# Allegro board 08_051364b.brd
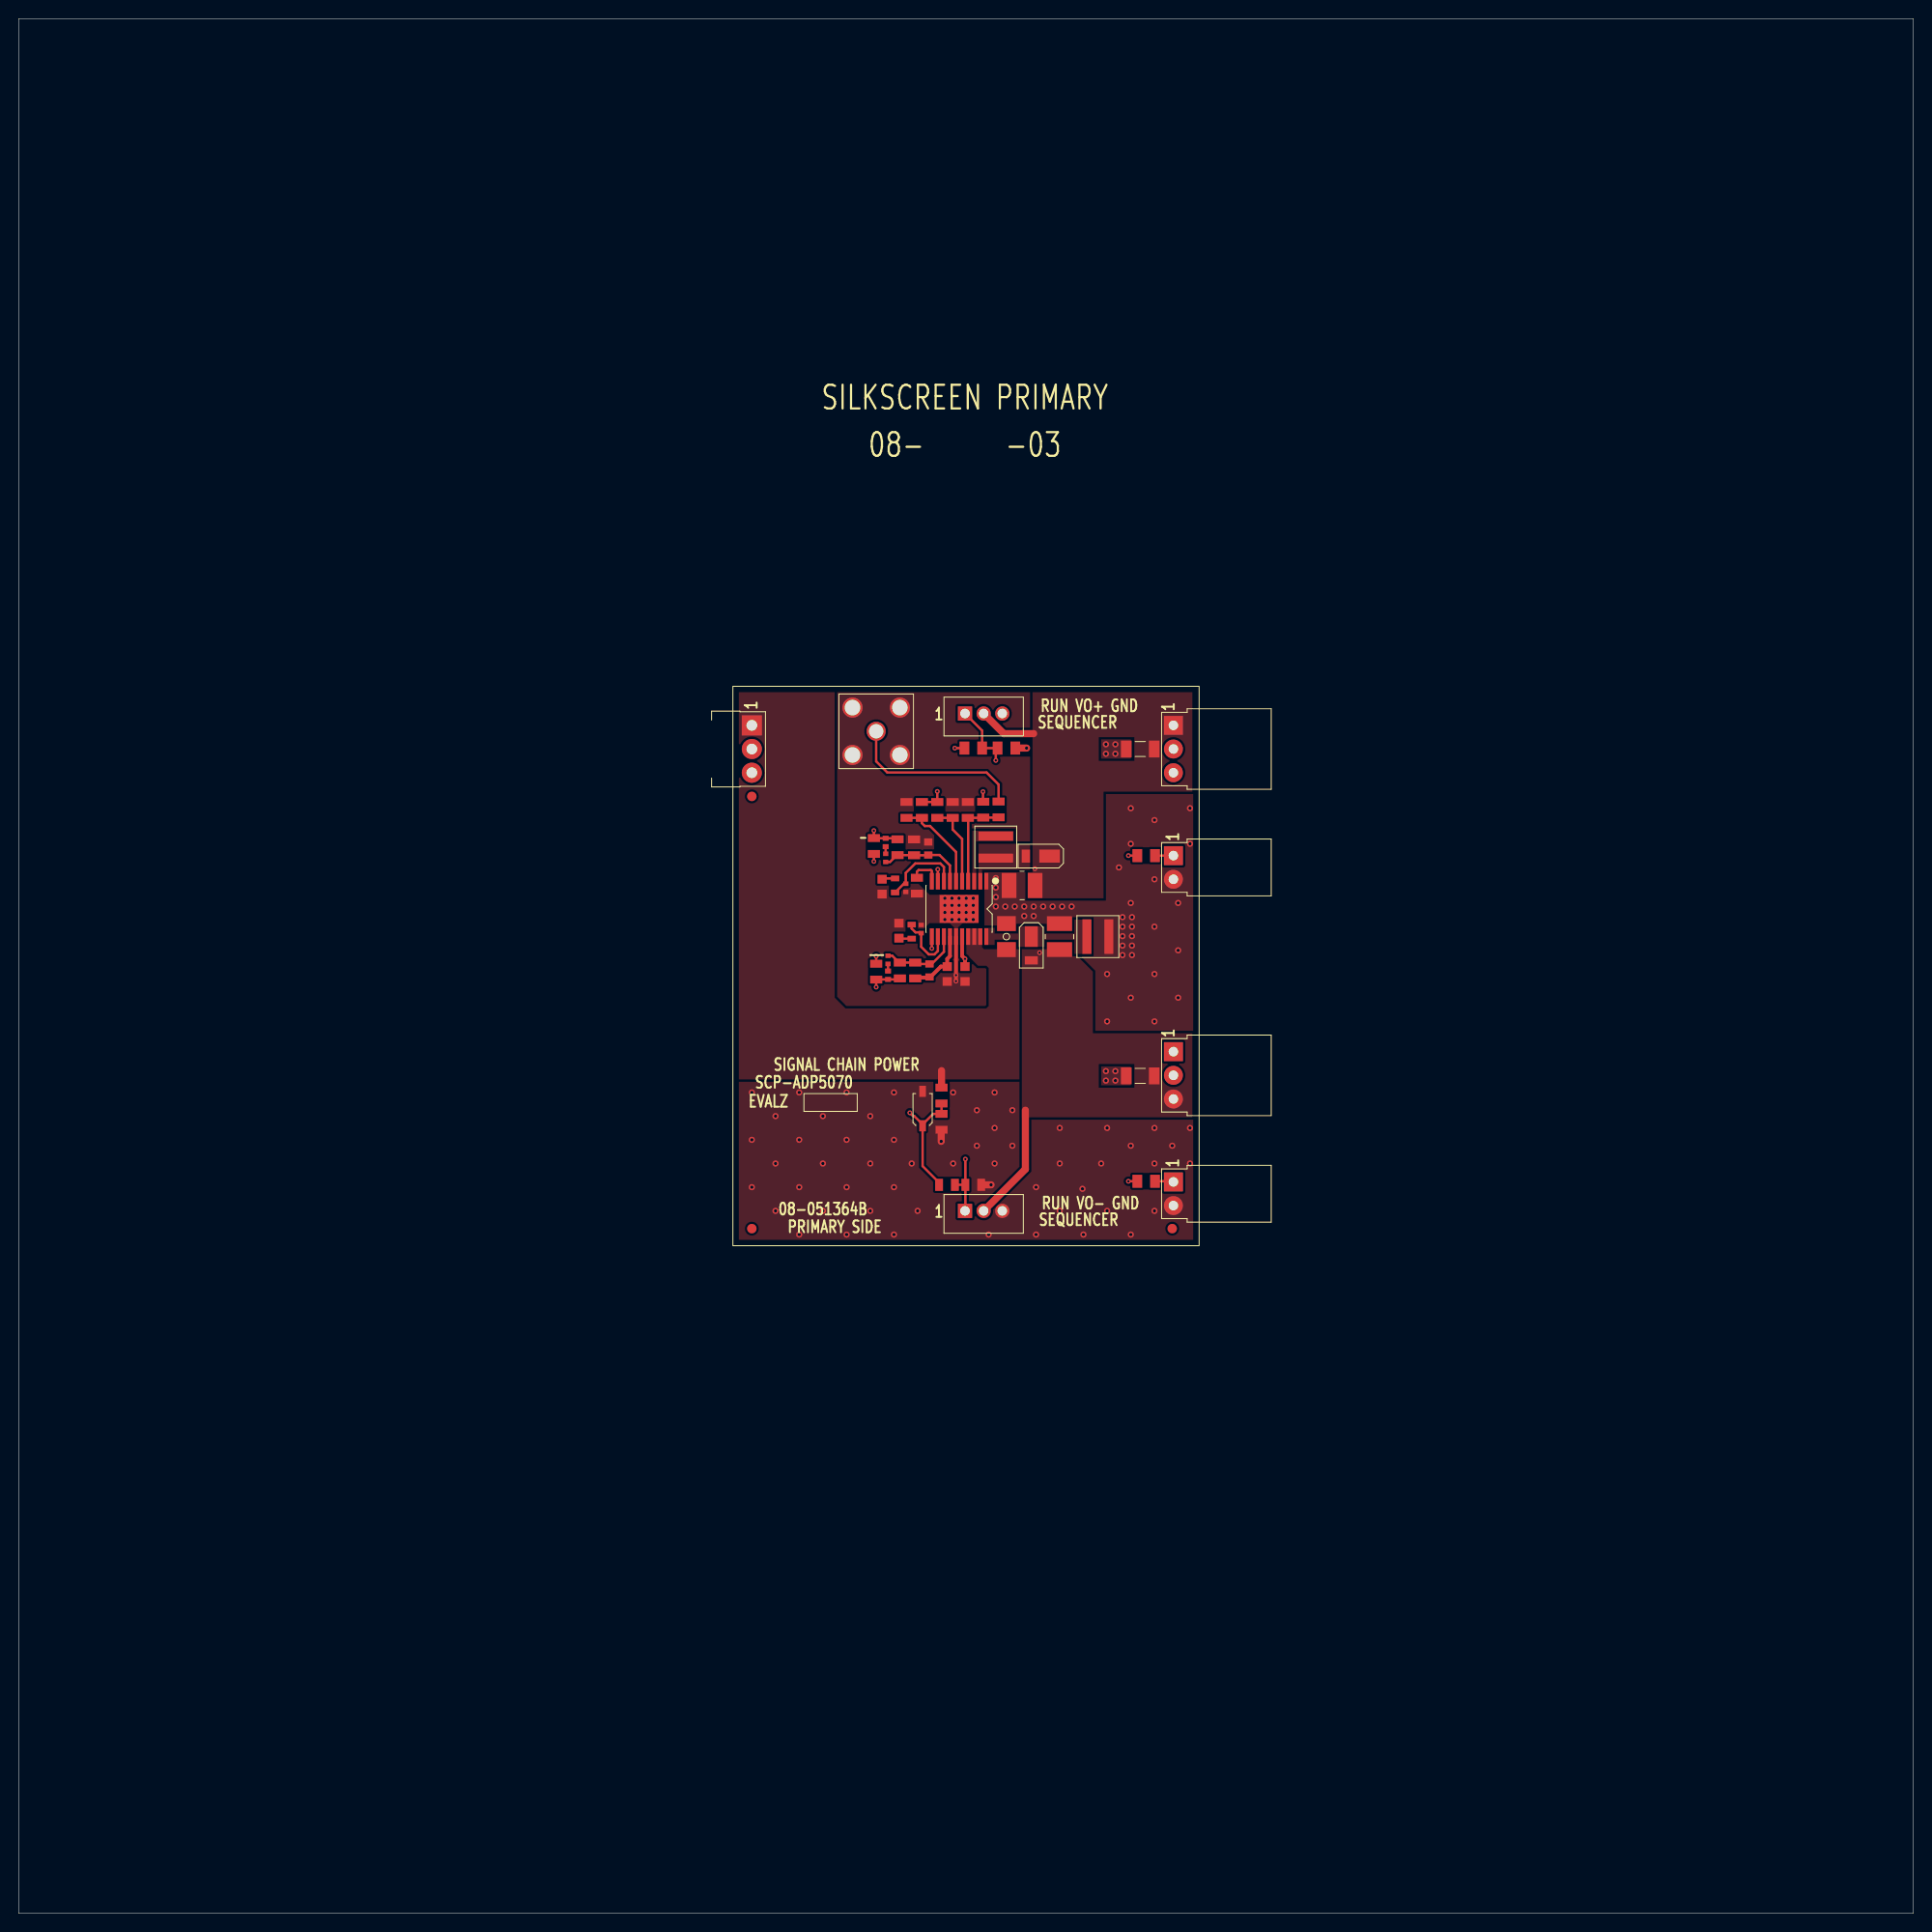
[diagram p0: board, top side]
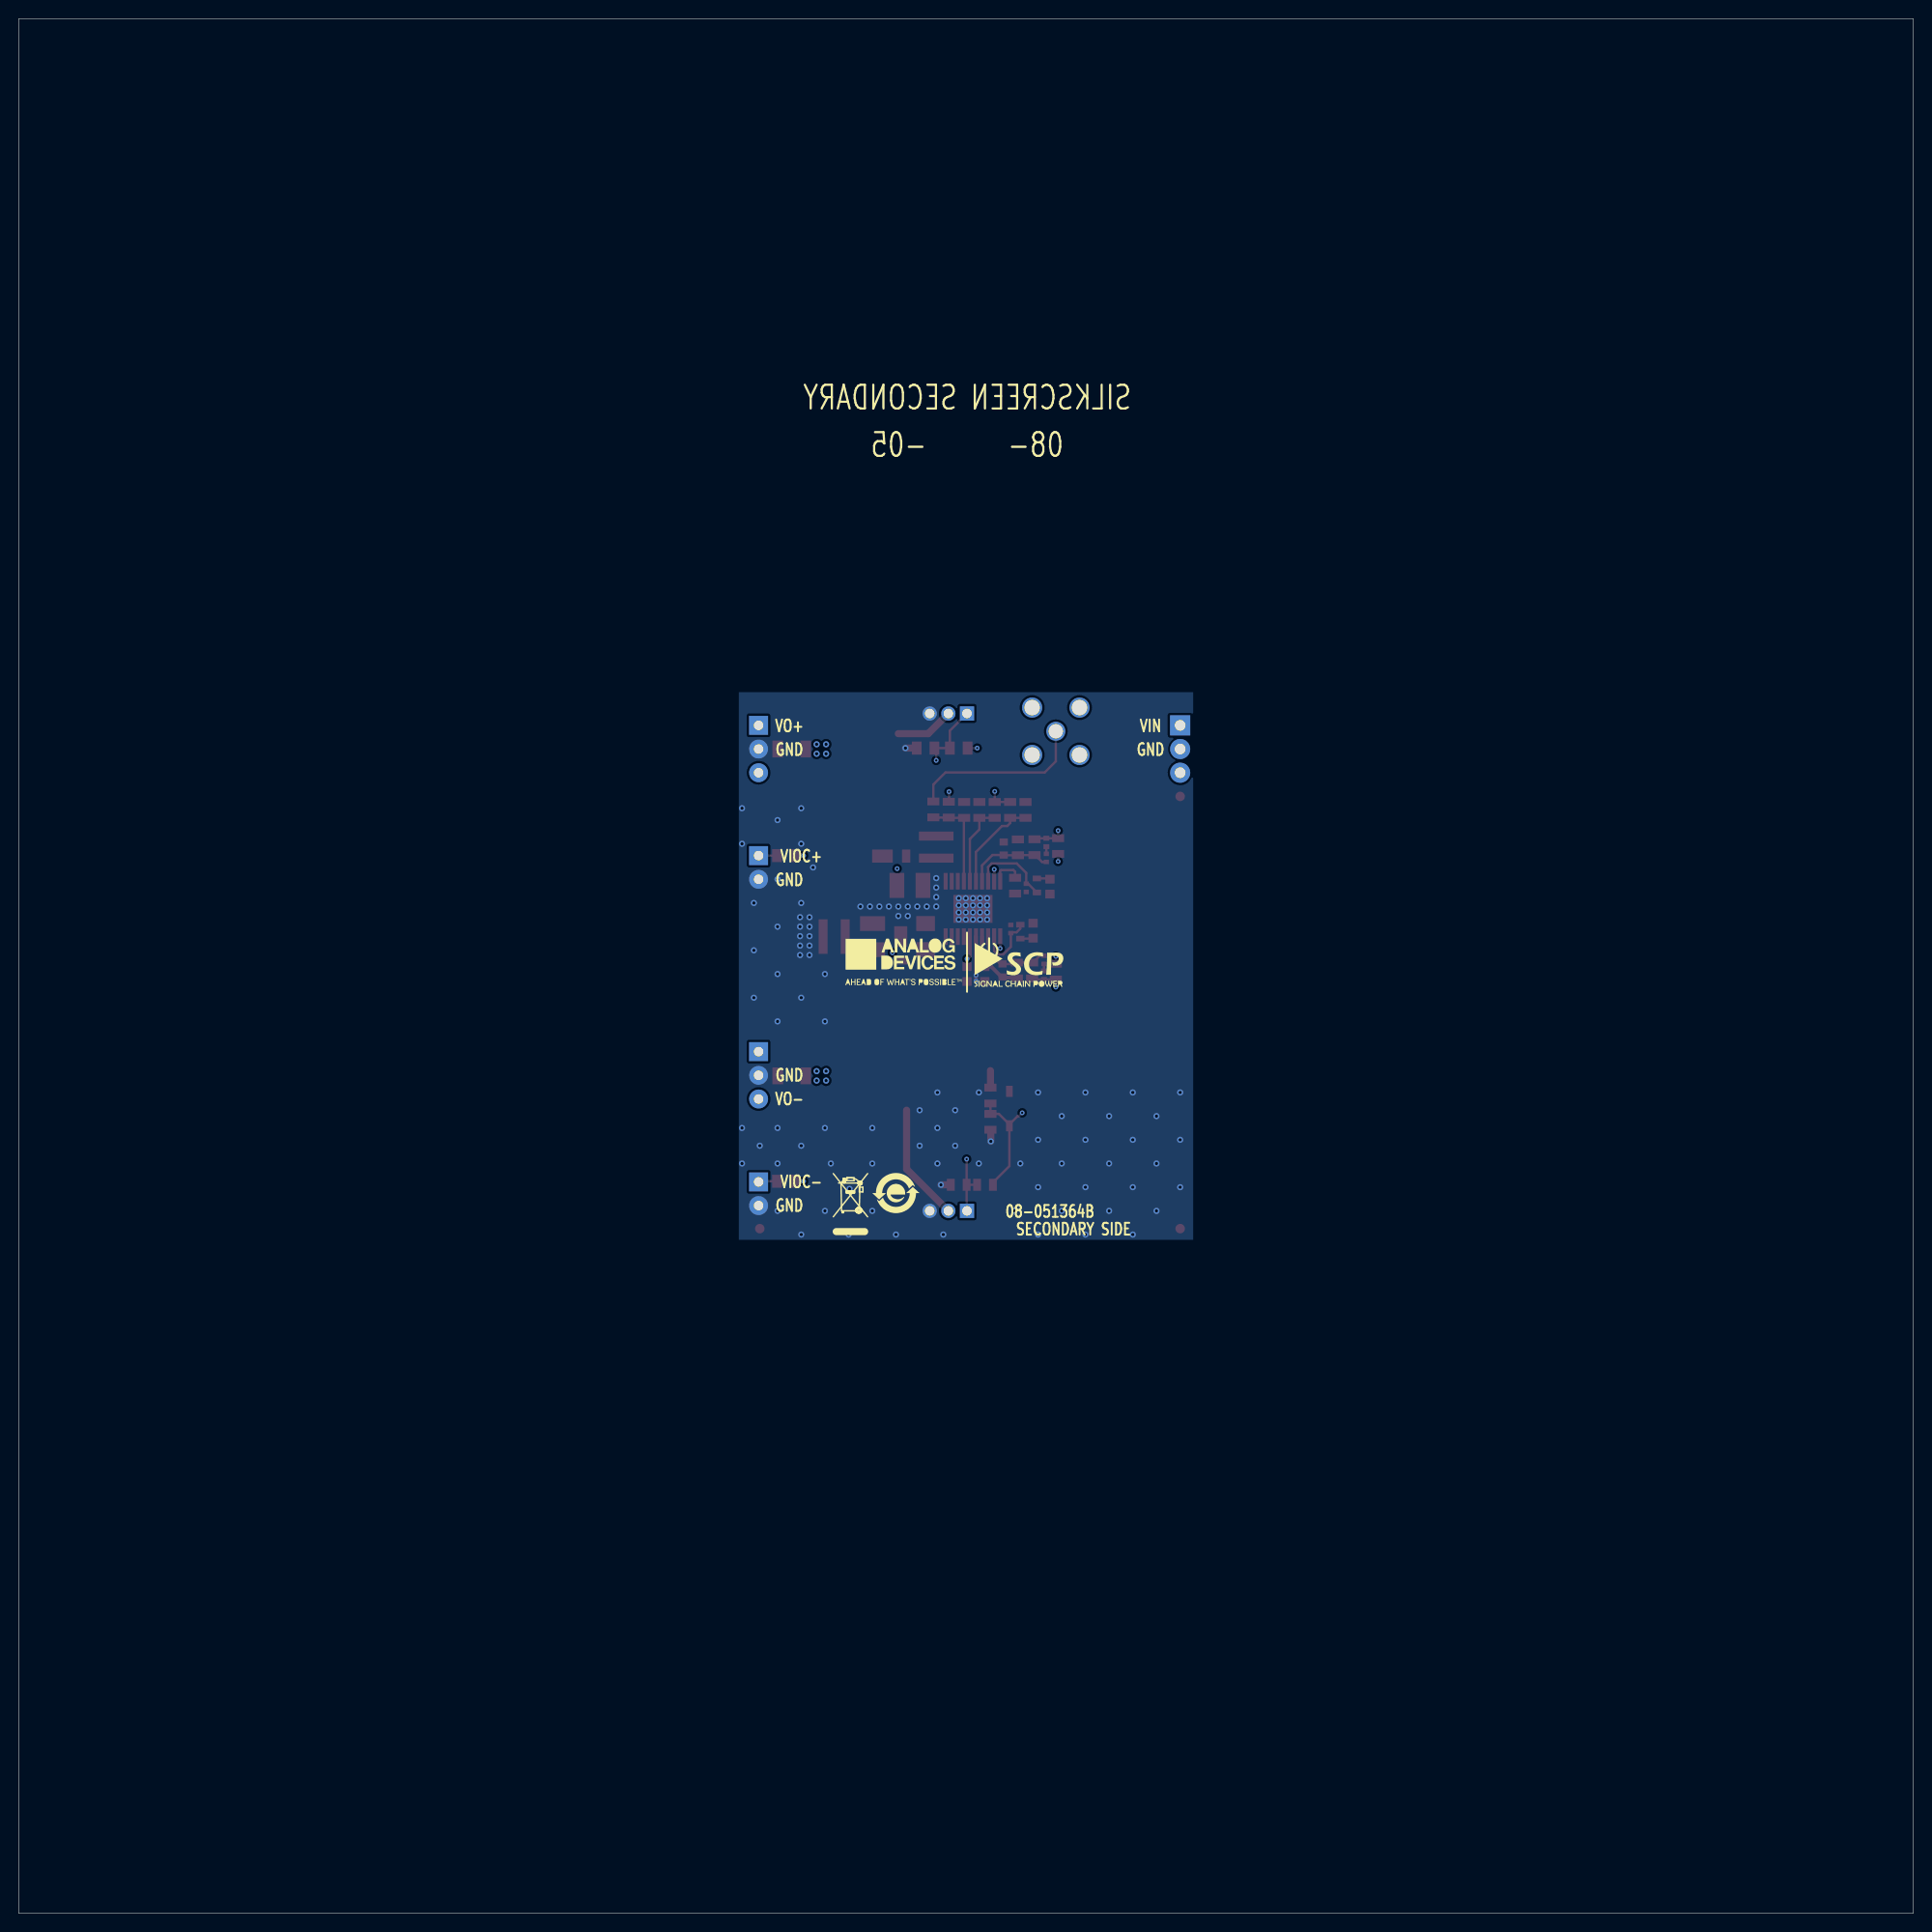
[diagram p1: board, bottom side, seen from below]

Outline 203.2 x 203.2 mm; copper layers: TOP, L2_GND, L3_SIG, BOTTOM. Coordinates in mm from the lower left corner of the outline.
Outline path: 0,203.2 203.2,203.2 203.2,0 0,0 0,203.2

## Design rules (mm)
constraint set DEFAULT: min track width 0.203

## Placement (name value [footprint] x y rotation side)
CC1  0.047uF  [C0603]  92.6 110.11 90 top
CC2  0.068uF  [C0603]  94.41 105.39 270 top
CFF1  TBD0402  [C0402]  92.98 113.2 270 top
CFF2  TBD0402  [C0402]  93.24 102.26 270 top
CHF3  TBD0402  [C0402]  95.14 109.98 270 top
CHF4  TBD0402  [C0402]  96.79 105.56 90 top
CIN1  10UF  [C1206H71]  105.94 104.75 90 top
COPT1  TBD0603  [C0603#2]  97.56 114.2 90 top
COPT2  TBD0603  [C0603#2]  97.68 101.12 90 top
COUT1  10uF  [C1210-2]  107.61 110.24 180 top
COUT1B  TBD1206  [C1206]  120.29 124.87 180 top
COUT2  10uF  [C1210-2]  111.63 104.75 270 top
COUT2B  TBD1206  [C1206]  120.29 89.82 0 top
CVREF  1UF  [C0603]  99.59 100.74 270 top
CVREG  1UF  [C0603]  101.49 100.74 270 top
D1  DFLS240-7  [DSML110W70H39]  109.62 113.39 180 top
D2  DFLS240-7  [DSML110W70H39]  108.6 103.81 270 top
D3  MMSZ5233B-7-F  [SOD123-3]  96.95 86.31 90 top
INPUT  PBC03SBAN  [CNTHMHDRRA1X3L300W100H145]  78.63 127.41 270 top
L1  6.8uH  [LSMSQ157H122]  104.79 114.35 90 top
L2  15uH  [LSMSQ157H161]  115.74 104.75 0 top
NOREF  -  []  78.63 127.41 0 top
NOREF#2  -  []  126.6 71.6 90 top
NOREF#3  -  []  126.6 71.6 90 top
NOREF#4  -  []  76.6 131.6 0 top
NOREF#5  -  []  126.6 131.6 180 top
NOREF#6  -  []  -273.05 -196.85 0 top
NOREF#7  -  []  76.6 131.6 0 top
NOREF#8  -  []  154.53 243.13 0 top
NOREF#9  -  []  -273.05 -196.85 0 top
NOREF#10  -  []  175.2 132.31 0 top
NOREF#11  -  []  30.04 19.38 0 top
NOREF#12  -  []  76.6 131.6 0 top
NOREF#13  -  []  185.95 28.91 0 top
NOREF#14  -  []  20.54 -100.96 0 top
NOREF#15  -  [unnamed#2]  78.63 119.79 0 top
NOREF#16  -  [unnamed#2]  123.72 73.43 0 top
NOREF#17  -  []  101.47 156.34 0 top
NOREF#18  -  []  78.63 127.41 0 top
NOREF#19  -  []  76.6 131.6 270 top
NOREF#20  -  [unnamed#2]  78.63 73.43 0 top
NOREF#21  -  []  76.6 71.6 0 top
NOREF#22  -  []  108.6 102.01 180 bottom
NOREF#23  -  []  109.11 77.24 180 bottom
NOREF#24  -  []  114.19 72.8 180 bottom
NOREF#25  -  []  95.9 102.01 180 bottom
OUTPUT1  PPPC031LGBN-RC  [CNHDRRA1X3H108]  123.84 127.41 270 top
OUTPUT2  PPPC031LGBN-RC  [CNHDRRA1X3H108]  123.84 92.42 270 top
P1  53253-0370  [CNTHMHDR1X3L315W144H224]  101.49 128.68 0 top
P2  53253-0370  [CNTHMHDR1X3L315W144H224]  101.49 75.34 0 top
R1  14.3K  [R0805]  98.98 87.71 270 top
R2  11K  [R0805]  98.98 84.89 270 top
R3  0  [R0805#2]  102.38 124.97 0 top
R4  TBD0805  [R0805#2]  105.94 124.97 0 top
R5  0  [R0805]  99.56 78.13 0 top
R6  TBD0805  [R0805]  102.38 78.13 0 top
R7  TBD0805  [R0805]  98.52 118.34 270 top
R8  TBD0805  [R0805]  100.17 118.34 90 top
R9  0  [R0805]  103.45 118.37 270 top
R10  TBD0805  [R0805]  101.8 118.34 90 top
R11  TBD0805  [R0805]  105.1 118.39 270 top
R12  TBD0805  [R0805]  96.34 110.21 270 top
R13  TBD0805  [R0805]  96.87 118.34 270 top
R14  TBD0805  [R0805]  95.22 118.34 90 top
R15  0  [R0805]  91.72 114.47 90 top
R16  0  [R0805]  91.97 100.99 270 top
R17  TBD0805  [R0805#2]  120.92 113.44 180 top
R18  TBD0805  [R0805#2]  120.92 78.51 0 top
RC1  12K  [R0603]  94 110.24 270 top
RC2  10K  [R0603]  95.78 105.29 90 top
RFB1  137K  [R0805]  96.03 114.33 270 top
RFB2  118K  [R0805]  96.16 101.12 270 top
RFF1  TBD0402  [R0402]  92.98 114.85 90 top
RFF2  TBD0402  [R0402]  93.24 100.61 270 top
RFT1  2.43MEG  [R0805]  94.25 114.34 270 top
RFT2  2.32MEG  [R0805]  94.51 101.12 270 top
SYNC  5-1814832-1  [CNTYCO1814832]  91.97 126.77 0 top
U1  ADP5070AREZ  [TSSOP20_PAD4_2X3]  100.86 107.72 180 top
VIOC1  PPPC021LGBN-RC  [CNTHFHDRRA1X2L220W335H108]  123.84 113.44 270 top
VIOC2  PPPC021LGBN-RC  [CNTHFHDRRA1X2L220W335H108]  123.84 78.45 270 top

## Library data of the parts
CC1 = CAP: User Part Number: UPN; Tolerance: 10; alternate symbols: (); part number: CAP_SM-0.047UF,16V,10,E022362,C0603; tolerance: 10
CC2 = CAP: User Part Number: UPN; Tolerance: 10; alternate symbols: (); part number: CAP_SM-0.068UF,16V,10,E022339,C0603; tolerance: 10
CFF1 CFF2 CHF3 CHF4 = CAP: User Part Number: UPN; alternate symbols: (C0402L_ALT); part number: CAP_SM-TBD0402,TBD0402,TBD0402,E000381,C0402; room: ADP5070_BOTTOM
CIN1 = CAP: Tolerance: 10; User Part Number: UPN; alternate symbols: (); part number: CAP_SM-10UF,25V,10,E022363,C1206H71; tolerance: 10
COPT1 COPT2 = CAP: User Part Number: UPN; alternate symbols: (C0603L, C0603L_ALT); part number: CAP_SM-TBD0603,TBD0603,TBD0603,E000382,C0603
COUT1 COUT2 = CAP: Tolerance: 10; User Part Number: UPN; alternate symbols: (); part number: CAP_SM-10UF,50V,10,E022361,C1210-2; tolerance: 10
COUT1B COUT2B = CAP: User Part Number: UPN; alternate symbols: (); part number: CAP_SM-TBD1206,TBD1206,TBD1206,E000384,C1206
CVREF CVREG = CAP: User Part Number: UPN; Tolerance: 10; alternate symbols: (); part number: CAP_SM-1UF,10V,10,E033698,C0603; tolerance: 10
D1 D2 = DIOSCHOTTKY: Tolerance: N/A; User Part Number: UPN; alternate symbols: (); part number: DIOSCHOTTKY_SM-DFLS240-7,40V,N/A,E019969,DSML110W70H39; tolerance: N/A
D3 = DIOZNR: Tolerance: 5; User Part Number: UPN; alternate symbols: (); part number: DIOZNR_SM-MMSZ5233B-7-F,N/A,5,E017917,SOD123-3; tolerance: 5
INPUT = CN3P: Tolerance: N/A; User Part Number: UPN; alternate symbols: (CNTHMHDRRA1X3L300W100H145_SCP); part number: CN3P_TH-PBC03SBAN,E034137,CNTHMHDRRA1X3L300W100H145; tolerance: N/A
L1 = IND: User Part Number: UPN; Tolerance: 20; alternate symbols: (); part number: IND_SM-6.8UH,20,E017909,LSMSQ157H122; tolerance: 20
L2 = IND: User Part Number: UPN; Tolerance: 20; alternate symbols: (); part number: IND_SM-15UH,20,E022386,LSMSQ157H161; tolerance: 20
OUTPUT1 OUTPUT2 = CN3P: User Part Number: UPN; Tolerance: N/A; alternate symbols: (CNHDRRA1X3H108_SCP); part number: CN3P_TH-PPPC031LGBN-RC,E034111,CNHDRRA1X3H108; tolerance: N/A
P1 P2 = CN3P: Tolerance: N/A; User Part Number: UPN; alternate symbols: (); part number: CN3P_TH-53253-0370,E033940,CNTHMHDR1X3L315W144H224; tolerance: N/A
R1 = RES: User Part Number: UPN; Tolerance: 1; alternate symbols: (R0805L); part number: RES_SM-14.3K,E012818,1/8W,1,R0805; tolerance: 1
R2 = RES: User Part Number: UPN; Tolerance: 1; alternate symbols: (R0805L); part number: RES_SM-11K,E003538,1/8W,1,R0805; tolerance: 1
R3 R5 R9 R15 R16 = RES: User Part Number: UPN; Tolerance: N/A; alternate symbols: (R0805L); part number: RES_SM-0,E004152,1/10W,N/A,R0805; tolerance: N/A
R4 R6-R8 R10-R14 R17 R18 = RES: User Part Number: UPN; alternate symbols: (R0805L); part number: RES_SM-TBD0805,E004051,TBD0805,TBD0805,R0805
RC1 = RES: User Part Number: UPN; Tolerance: 1; alternate symbols: (R0603L); part number: RES_SM-12K,E018193,1/10W,1,R0603; tolerance: 1
RC2 = RES: User Part Number: UPN; Tolerance: 1; alternate symbols: (R0603L); part number: RES_SM-10K,E017856,1/16W,1,R0603; tolerance: 1
RFB1 = RES: User Part Number: UPN; Tolerance: 1; alternate symbols: (R0805L); part number: RES_SM-137K,E003652,1/8W,1,R0805; tolerance: 1
RFB2 = RES: User Part Number: UPN; Tolerance: 1; alternate symbols: (R0805L); part number: RES_SM-118K,E020283,1/8W,1,R0805; tolerance: 1
RFF1 RFF2 = RES: User Part Number: UPN; alternate symbols: (R0402L,R0402L_ALT); part number: RES_SM-TBD0402,E004049,TBD0402,TBD0402,R0402; room: ADP5070_BOTTOM
RFT1 = RES: User Part Number: UPN; Tolerance: 1; alternate symbols: (R0805L); part number: RES_SM-2.43MEG,E022341,1/8W,1,R0805; tolerance: 1
RFT2 = RES: User Part Number: UPN; Tolerance: 1; alternate symbols: (R0805L); part number: RES_SM-2.32MEG,E022342,1/8W,1,R0805; tolerance: 1
SYNC = CNBNC5P: Tolerance: N/A; User Part Number: UPN; alternate symbols: (); part number: CNBNC5P_TH-5-1814832-1,E010606,CNTYCO1814832; tolerance: N/A
U1 = ADP5070_V2: Tolerance: N/A; User Part Number: UPN; alternate symbols: (); part number: ADP5070_V2_SM-ADP5070AREZ,E017326,TSSOP20_PAD4_2X3; tolerance: N/A
VIOC1 VIOC2 = CN2P: Tolerance: N/A; User Part Number: UPN; alternate symbols: (CNTHFHDRRA1X2L220W335H108_SCP); part number: CN2P_TH-PPPC021LGBN-RC,E034113,CNTHFHDRRA1X2L220W335H108; tolerance: N/A

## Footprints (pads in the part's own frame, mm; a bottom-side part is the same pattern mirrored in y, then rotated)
C0402
  rect 0.483x0.559 smd: 1(-0.438,0) 2(0.438,0)
C0603
  rect 0.94x0.991 smd: 1(-0.8,0) 2(0.8,0)
C0603#2
  rect 0.762x0.889 smd: 1(-0.7,0) 2(0.7,0)
C1206
  rect 1.143x1.803 smd: 1(-1.5,0) 2(1.5,0)
C1206H71
  rect 1.6x2.007 smd: 1(-1.397,0) 2(1.397,0)
C1210-2
  rect 1.575x2.692 smd: 1(-1.397,0) 2(1.397,0)
CNHDRRA1X3H108
  rect 2.032x2.032 hole 1.016: 1(0,0)
  round 2.032 hole 1.016: 2(2.54,0) 3(5.08,0)
CNTHFHDRRA1X2L220W335H108
  rect 2.032x2.032 hole 1.016: 1(0,0)
  round 2.032 hole 1.016: 2(2.54,0)
CNTHMHDR1X3L315W144H224
  rect 1.524x1.524 hole 1.016: 1(0,0)
  round 1.524 hole 1.016: 2(2,0) 3(4,0)
CNTHMHDRRA1X3L300W100H145
  rect 2.159x2.159 hole 1.143: 1(0,0)
  round 2.159 hole 1.143: 2(2.54,0) 3(5.08,0)
CNTYCO1814832
  round 2.032 hole 1.524: 1(0,0)
  round 2.159 hole 1.651: 2(-2.54,2.54) 3(2.54,2.54) 4(2.54,-2.54) 5(-2.54,-2.54)
DSML110W70H39
  rect 0.889x1.397 smd: A(1.605,0)
  rect 2.21x1.397 smd: C(-0.945,0)
LSMSQ157H122
  rect 0.965x3.708 smd: 1(-1.181,0) 2(1.181,0)
LSMSQ157H161
  rect 0.965x3.708 smd: 1(-1.181,0) 2(1.181,0)
R0402
  rect 0.533x0.635 smd: 1(-0.45,0) 2(0.45,0)
R0603
  rect 0.61x0.889 smd: 1(-0.75,0) 2(0.75,0)
R0805
  rect 0.838x1.295 smd: 1(-0.85,0) 2(0.85,0)
R0805#2
  rect 1.041x1.397 smd: 1(-0.95,0) 2(0.95,0)
SOD123-3
  rect 1.194x0.711 smd: A(1.847,0) C(-1.847,0)
TSSOP20_PAD4_2X3
  rect 0.432x1.778 smd: 1(-2.925,-2.97) 2(-2.275,-2.97) 3(-1.625,-2.97) 4(-0.975,-2.97) 5(-0.325,-2.97) 6(0.325,-2.97) 7(0.975,-2.97) 8(1.625,-2.97) 9(2.275,-2.97) 10(2.925,-2.97) 11(2.925,2.97) 12(2.275,2.97) 13(1.625,2.97) 14(0.975,2.97) 15(0.325,2.97) 16(-0.325,2.97) 17(-0.975,2.97) 18(-1.625,2.97) 19(-2.275,2.97) 20(-2.925,2.97)
  rect 4.191x2.997 smd: PAD(0,0)
unnamed#2
  round 1.016 smd: (0,0)

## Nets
AGND: CC1.1 CC2.1 CHF3.2(N2) CHF4.2(N2) CIN1.2(N2) COPT1.2(N2) COUT1.2(N2) COUT1B.2(N2) COUT2.1 COUT2B.1 CVREF.2(N2) CVREG.2(N2) D3.A(P) INPUT.2 L2.2(N2) OUTPUT1.2 OUTPUT2.2 P1.3(N3) P2.3(N3) R2.2(N2) R4.2(N2) R6.2(N2) R8.2(N2) R10.2(N2) R12.2(N2) R14.2(N2) RFB1.1 SYNC.2 SYNC.3 SYNC.4 SYNC.5(SH4) U1.1 U1.15 U1.PAD VIOC1.2(N2) VIOC2.2(N2)
VIN+: CIN1.1 INPUT.1 R1.1 U1.17 U1.18 U1.19
COMP1: CHF3.1 RC1.2(N2) U1.8
COMP2: CHF4.1 RC2.2(N2) U1.12
EN1: P1.1 R3.2(N2) R4.1 U1.9
EN2: P2.1 R5.2(N2) R6.1 U1.11
FB1: CFF1.2(N2) COPT1.1 RFB1.2(N2) RFT1.2(N2) U1.7
FB2: CFF2.1 COPT2.2(N2) RFB2.1 RFT2.1 U1.13
INBK: L1.2(N2) U1.3
SEQ: R7.2(N2) R8.1 U1.5
SLEW: R13.2(N2) R14.1 U1.6
SS: R12.1 U1.10
SW1: D1.A(P) L1.1 U1.2
SW2: D2.C L2.1 U1.20
SYNC: R9.2(N2) R10.1 R11.2(N2) U1.4
UNNAMED_2_CAP_I20_N2: CC1.2(N2) RC1.1
UNNAMED_2_CAP_I23_N1: CFF1.1 RFF1.1
UNNAMED_2_CAP_I30_N2: CC2.2(N2) RC2.1
UNNAMED_2_CAP_I33_N2: CFF2.2(N2) RFF2.1
UNNAMED_2_CN2P_I108_N1: R17.1 VIOC1.1
UNNAMED_2_CN2P_I109_N1: R18.2(N2) VIOC2.1
UNNAMED_2_CNBNC5P_I90_CNTR: R11.1 SYNC.1
UNNAMED_2_RES_I134_N2: R15.2(N2) R17.2(N2) RFF1.2(N2) RFT1.1
UNNAMED_2_RES_I135_N1: R16.2(N2) R18.1 RFF2.2(N2) RFT2.2(N2)
V_EN: D3.C R1.2(N2) R2.1 R3.1 R5.1
VO+: COUT1.1 COUT1B.1 D1.C OUTPUT1.1 P1.2 R15.1
VO-: COUT2.2(N2) COUT2B.2(N2) D2.A(P) OUTPUT2.3(N3) P2.2 R16.1
VREF: COPT2.1 CVREF.1 RFB2.2(N2) U1.14
VREG: CVREG.1 R7.1 R9.1 R13.1 U1.16(VREG)

Pads without a net: INPUT 3; OUTPUT1 3; OUTPUT2 1

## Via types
v1: diameter 0.508, hole 0.254, TOP to BOTTOM, 19 vias
v2: diameter 0.66, hole 0.356, TOP to BOTTOM, 126 vias

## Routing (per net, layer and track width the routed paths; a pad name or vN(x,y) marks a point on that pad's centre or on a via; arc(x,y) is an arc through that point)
AGND: length 8.3
  TOP w0.406: 100.53,99.97 v1(100.53,99.98) v1(100.53,100.61) 100.53,100.62 U1.15
  TOP w0.762: R6.2 v2(104.29,78.13) ; R4.2 v2(108.1,124.97) ; 98.94,84.03 v2(98.94,82.79)
  vias: v2(78.63,88.04) v2(78.63,82.96) v2(78.63,77.88) v2(81.17,85.5) v2(81.17,80.42) v2(81.17,75.34) v2(83.71,88.04) v2(83.71,82.96) v2(83.71,77.88) v2(83.71,72.8) v2(86.25,85.5) v2(86.25,80.42) v2(86.25,75.34) v2(88.79,88.04) v2(88.79,82.96) v2(88.79,77.88) v2(88.79,72.8) v2(91.33,85.5) v2(91.33,80.42) v2(91.33,75.34) v2(93.87,88.04) v2(93.87,82.96) v2(93.87,77.88) v2(93.87,72.8) v2(95.78,80.42) v2(96.41,75.34) v2(99.33,108.87) v2(99.33,108.1) v2(99.33,107.34) v2(99.33,106.58) v2(100.1,108.87) v2(100.1,108.1) v2(100.1,107.34) v2(100.1,106.58) v2(100.22,88.04) v2(100.22,80.42) v2(100.86,108.87) v2(100.86,108.1) v2(100.86,107.34) v2(100.86,106.58) v2(101.62,108.87) v2(101.62,108.1) v2(101.62,107.34) v2(101.62,106.58) v2(102.38,108.87) v2(102.38,108.1) v2(102.38,107.34) v2(102.38,106.58) v2(102.76,86.13) v2(102.76,82.32) v2(104.03,72.8) v2(104.67,88.04) v2(104.67,84.23) v2(104.67,80.42) v2(104.79,111.03) v2(104.79,110.01) v2(104.79,108.99) v2(104.79,107.98) v2(105.81,107.98) v2(106.57,86.13) v2(106.57,82.32) v2(106.83,107.98) v2(107.84,107.98) v2(107.84,106.96) v2(108.86,107.98) v2(108.86,106.96) v2(109.11,77.88) v2(109.11,72.8) v2(109.87,107.98) v2(110.89,107.98) v2(111.65,84.23) v2(111.65,80.42) v2(111.65,75.34) v2(111.91,107.98) v2(112.92,107.98) v2(114.09,77.7) v2(114.19,72.8) v2(116.1,80.42) v2(116.61,125.38) v2(116.61,124.36) v2(116.61,90.32) v2(116.61,89.31) v2(116.73,100.74) v2(116.73,95.66) v2(116.73,84.23) v2(116.73,75.34) v2(117.62,125.38) v2(117.62,124.36) v2(117.62,90.32) v2(117.62,89.31) v2(118,112.17) v2(118.38,106.83) v2(118.38,105.82) v2(118.38,104.8) v2(118.38,103.79) v2(118.38,102.77) v2(119.27,118.52) v2(119.27,114.71) v2(119.27,108.36) v2(119.27,98.2) v2(119.27,82.32) v2(119.27,72.8) v2(119.4,106.83) v2(119.4,105.82) v2(119.4,104.8) v2(119.4,103.79) v2(119.4,102.77) v2(121.81,117.25) v2(121.81,110.9) v2(121.81,105.82) v2(121.81,100.74) v2(121.81,95.66) v2(121.81,84.23) v2(121.81,80.42) v2(121.81,75.34) v2(123.72,82.32) v2(124.35,108.36) v2(124.35,103.28) v2(124.35,98.2) v2(125.62,118.52) v2(125.62,114.71) v2(125.62,84.23) v2(125.62,80.42)
VIN+: length 1.8
  TOP w0.762: R1.1 98.98,90.38
COMP1: length 8.9
  TOP w0.254: RC1.2 94.93,110.42 CHF3.1 95.14,111.58 96.16,112.6 98.85,112.6 99.23,112.22 U1.8
COMP2: length 6.9
  TOP w0.254: U1.12 98.58,103.21 98.22,102.85 97.61,102.85 96.79,103.66 CHF4.1 96.71,105.21 96.18,105.21 95.78,105.62 RC2.2
EN1: length 40.1
  TOP w0.254: U1.9 98.58,111.95 v1(98.57,111.97) ; v1(104.79,123.65) 104.79,124.78 R4.1 R3.2 103.33,126.84 P1.1
  L3_SIG w0.254: v1(98.57,111.97) 91.13,111.97 90.65,112.45 90.65,116.54 93.19,119.08 103.7,119.08 104.79,120.17 v1(104.79,123.65)
EN2: length 42.3
  TOP w0.254: R6.1 101.53,75.38 P2.1 ; R6.1 R5.2 ; R6.1 v1(101.53,80.89) ; U1.11 97.93,103.49 v1(97.94,103.48)
  L3_SIG w0.254: v1(101.53,80.89) 101.53,88 90.7,98.83 90.7,103.02 91.46,103.79 97.63,103.79 v1(97.94,103.48)
FB1: length 9.4
  TOP w0.254: CFF1.2 93.45,112.76 94.18,113.49 RFT1.2 96.02,113.49 RFB1.2 97.53,113.48 COPT1.1 98.76,113.5 99.88,112.38 U1.7
FB2: length 8.5
  TOP w0.254: CFF2.1 93.69,102.7 94.42,101.97 RFT2.1 RFB2.1 96.31,101.82 COPT2.2 97.92,101.82 99.23,103.13 U1.13
SEQ: length 8.9
  TOP w0.254: R7.2 R8.1 100.17,116.23 101.18,115.22 U1.5
SLEW: length 10.3
  TOP w0.254: R14.1 R13.2 96.87,116.92 97.17,116.61 97.75,116.61 100.53,113.83 U1.6
SS: length 3.5
  TOP w0.254: U1.10 97.93,111.79 97.83,111.89 96.51,111.89 96.34,111.71 R12.1
SYNC: length 10.1
  TOP w0.254: U1.4 101.83,117.46 R10.1 103.42,117.49 R9.2 105.07,117.52 R11.2
UNNAMED_2_CAP_I20_N2: length 1.4
  TOP w0.254: RC1.1 92.68,110.99 CC1.2
UNNAMED_2_CAP_I23_N1: length 0.8
  TOP w0.254: CFF1.1 RFF1.1
UNNAMED_2_CAP_I30_N2: length 1.4
  TOP w0.254: CC2.2 94.46,104.54 RC2.1
UNNAMED_2_CAP_I33_N2: length 0.8
  TOP w0.254: RFF2.1 CFF2.2
UNNAMED_2_CN2P_I108_N1: length 2
  TOP w0.254: R17.1 VIOC1.1
UNNAMED_2_CN2P_I109_N1: length 2
  TOP w0.254: R18.2 123.78,78.51 VIOC2.1
UNNAMED_2_CNBNC5P_I90_CNTR: length 19.2
  TOP w0.254: SYNC.1 91.97,123.55 93.16,122.35 103.8,122.35 105.1,121.06 R11.1
UNNAMED_2_RES_I134_N2: length 32.8
  TOP w0.254: R17.2 v1(119.02,113.44) ; RFT1.1 94.15,115.3 RFF1.2 91.74,115.3 R15.2 v1(91.72,116.12)
  L3_SIG w0.254: v1(91.72,116.12) 93.77,114.07 118.38,114.07 v1(119.02,113.44)
UNNAMED_2_RES_I135_N1: length 40
  TOP w0.254: RFT2.2 94.4,100.16 RFF2.2 91.99,100.16 R16.2 v1(91.97,99.34) ; R18.1 v1(119.02,78.51)
  L3_SIG w0.254: v1(119.02,78.51) 98.19,99.34 v1(91.97,99.34)
V_EN: length 63.3
  TOP w0.254: v1(95.57,85.85) 95.93,85.5 96.06,85.5 96.95,84.61 ; v1(100.4,124.97) R3.1 ; 96.95,84.61 98.07,85.74 R2.1 R1.2 ; 96.95,84.61 D3.C 96.95,80.14 98.71,78.37 R5.1
  L3_SIG w0.254: v1(95.57,85.85) 95.57,92.31 88.54,99.34 88.54,117.63 92.48,121.57 97,121.57 v1(100.4,124.97)
VO+: length 24.7
  TOP w0.254: R15.1 v1(91.72,112.82)
  TOP w0.762: P1.2 105.65,126.52 108.86,126.52
  L3_SIG w0.305: v1(91.72,112.82) 91.83,112.93 108.1,112.93 v1(108.99,112.04)
VO-: length 32.3
  TOP w0.254: R16.1 v1(91.97,102.64)
  TOP w0.762: P2.2 107.97,79.82 107.97,86.13
  L3_SIG w0.305: v1(91.97,102.64) 93.34,101.27 107.74,101.27 v1(109.49,103.02)
VREF: length 7.3
  TOP w0.406: RFB2.2 96.25,100.36 97.62,100.36 COPT2.1 97.78,100.42 98.9,101.54 CVREF.1 99.59,102.36 99.88,102.66 U1.14
VREG: length 44
  TOP w0.254: v1(103.42,120.3) 103.42,119.24 R9.1 ; R13.1 R7.1 v1(98.52,120.32)
  TOP w0.406: U1.16 101.18,102.67 v1(101.49,102.36) CVREG.1
  L3_SIG w0.254: v1(101.49,102.36) 93.92,109.93 90.62,109.93 89.58,110.98 89.58,117.07 92.83,120.32 v1(98.52,120.32) 103.4,120.32 v1(103.42,120.3)

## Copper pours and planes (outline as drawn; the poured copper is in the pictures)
AGND on TOP: 99.1,99.47 99.1,100.41 101.97,100.41 101.97,99.47
AGND on TOP: 119.27,125.88 119.27,123.85 116.1,123.85 116.1,125.88
AGND on TOP: 77.24,130.96 125.96,130.96 125.96,125.88 119.27,125.88 119.27,123.85 116.48,123.85 116.48,122.58 125.96,122.58 125.96,92.1 119.02,92.1 119.02,90.83 119.27,90.83 119.27,88.8 125.96,88.8 125.96,72.24 77.24,72.24 ; 15 cut-outs
AGND on BOTTOM: 77.24,130.96 125.96,130.96 125.96,72.24 77.24,72.24 ; 9 cut-outs
AGND on L2_GND: 107.33,89.18 107.33,85.12 125.95,85.12 125.95,72.24 77.24,72.24 77.24,89.18
AGND on L2_GND: 107.97,108.87 107.97,108.61 116.61,108.61 116.61,120.04 125.96,120.04 125.96,94.64 115.46,94.64 115.46,101.12 113.81,102.77 113.81,106.58 113.56,106.58 113.56,102.64 115.21,100.99 115.21,94.39 125.88,94.39 125.88,85.37 107.59,85.37 107.59,103.41 109.75,103.41 109.75,106.58 109.49,106.58 109.49,103.66 107.59,103.66 107.59,106.58 107.33,106.58 107.33,89.44 77.24,89.44 77.24,123.47 77.24,123.47 77.24,130.96 87.52,130.96 87.52,98.2 88.67,97.06 103.78,97.06 104.03,97.31 104.03,103.15 104.41,103.53 104.41,106.58 104.16,106.58 104.16,103.66 103.78,103.28 103.78,97.44 103.65,97.31 88.79,97.31 87.78,98.33 87.78,130.96 108.48,130.96 108.48,111.66 108.73,111.66 108.73,130.96 125.88,130.96 125.88,120.3 116.35,120.3 116.35,108.87 ; 4 cut-outs
AGND on L3_SIG: 77.24,130.96 125.96,130.96 125.96,72.24 77.24,72.24 ; 9 cut-outs
VIN+ on TOP: 77.24,130.96 86.89,130.96 87.52,130.96 87.52,98.2 88.67,97.06 103.78,97.06 104.03,97.31 104.03,101.37 103.78,101.63 102.89,101.63 101.62,102.9 101.62,105.64 103.32,105.64 103.32,103.61 103.52,103.41 104.92,103.41 104.92,104.17 106.95,104.17 106.95,103.41 107.33,103.41 107.33,89.44 77.24,89.44 77.24,123.47 77.24,126.01
INBK on TOP: 102.28,109.81 102.69,109.81 102.69,114.96 106.7,114.96 106.7,116.11 102.28,116.11
SW1 on TOP: 102.94,109.81 102.94,114.71 108.48,114.71 108.48,111.91 103.32,111.91 103.32,109.81
SW2 on TOP: 103.57,105.69 104.67,105.69 104.67,105.08 107.21,105.08 107.21,105.87 110.03,105.87 110.03,105.08 113.23,105.08 113.23,106.58 115.03,106.58 115.03,102.9 113.23,102.9 113.23,104.42 110.03,104.42 110.03,103.66 107.21,103.66 107.21,104.42 104.67,104.42 104.67,103.86 103.57,103.86
VO+ on TOP: 108.22,111.66 108.73,111.66 108.73,130.96 125.88,130.96 125.88,120.3 116.35,120.3 116.35,108.87 108.22,108.87 ; 1 cut-out
VO- on TOP: 125.88,85.37 125.88,94.39 115.21,94.39 115.21,100.99 113.56,102.64 112.97,102.64 112.97,104.17 110.28,104.17 110.28,103.41 107.59,103.41 107.59,85.37 ; 1 cut-out

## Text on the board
Ref Des/Silkscreen Bottom: VIN | GND | SECONDARY SIDE | 08-051364B | VIOC+ | VIOC- | VO+ | VO-
Ref Des/Silkscreen Top: EVALZ | SCP-ADP5070 | 08-051364B | PRIMARY SIDE | SIGNAL CHAIN POWER | SEQUENCER | RUN VO+ GND | RUN VO- GND
PAGE_OUTLINE: B | AS PER ECR-086560 | 07MAY19 | J. VIERNES
DIMENSION: REF | DIA MAX/SEE DETAIL 15
User.15: 15.    THRU VIAS TO BE FILLED WITH SOLDERMASK.
User.17: L2 GND | 08-      -07
User.18: L3 SIG | 08-      -08
User.45: FIGURE | SIZE | 10.0 | 14.0 | 40.0 | 45.0 | 60.0 | 65.0 | PLATED | FINISHED HOLES IN MILS | ALL UNITS ARE IN MILS | QTY | 19 | 126 | 16 | 3 | 1 | 4 | TOLERANCE/NOTES
